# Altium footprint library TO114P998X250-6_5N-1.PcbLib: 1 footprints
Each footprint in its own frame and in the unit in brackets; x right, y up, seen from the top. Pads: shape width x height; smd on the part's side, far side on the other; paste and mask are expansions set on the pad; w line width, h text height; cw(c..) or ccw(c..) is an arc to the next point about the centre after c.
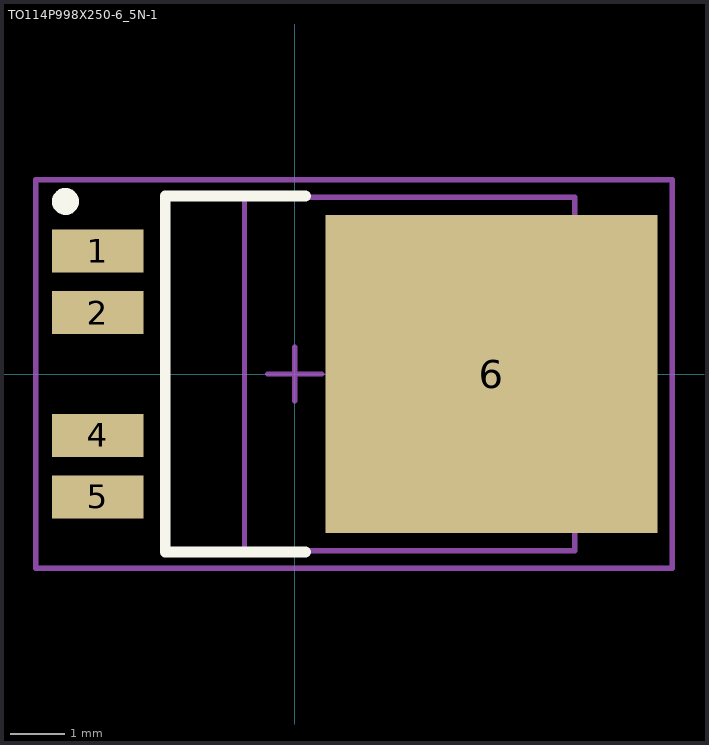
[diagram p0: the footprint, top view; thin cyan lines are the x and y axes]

## TO114P998X250-6_5N-1 [mm] "TO,1.14mm pitch;5 pin,9.98mm L X 6.12mm W X 2.50mm H body"
height 2.5
pads (5):
  rect 1.7x0.8 smd paste+0 mask+0: 1(-3.65,2.28)
  rect 1.7x0.8 smd mask+0: 2(-3.65,1.14) 4(-3.65,-1.14) 5(-3.65,-2.28)
  rect 6.15x5.9 smd paste+0 mask+0: 6(3.65,0)
Top Overlay:
  circle w0.25: c-4.25,3.2 r0.125
  lines w0.2: 0.2,-3.3 -2.4,-3.3 -2.4,3.3 0.2,3.3
M3 (ASY_Text_Top):
  text ".DESIGNATOR" at 0,0 h1.2
M13 (CMP_Body_OTL_Top):
  lines w0.1: -0.93,-3.275 -0.93,3.275 5.19,3.275 5.19,-3.275 -0.93,-3.275
M15 (CMP_Courtyard_Top):
  lines w0.1: -0.5,0 0.5,0 ; 0,-0.5 0,0.5 ; -4.8,-3.6 7,-3.6 7,3.6 -4.8,3.6 -4.8,-3.6
3D body "PG-TO252-5-11_C63078-A6553-C041-04-0004.stp": height 2.36, standoff 0, extent -3.878,-3.25 6.103,3.25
